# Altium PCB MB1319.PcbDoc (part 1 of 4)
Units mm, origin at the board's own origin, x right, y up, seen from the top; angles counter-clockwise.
Board outline 70 x 82.5 mm, 2 copper layers (Top Layer, Bottom Layer), stack 1.571 mm thick; 252 components, 179 nets, 814 pads, 1000 vias.
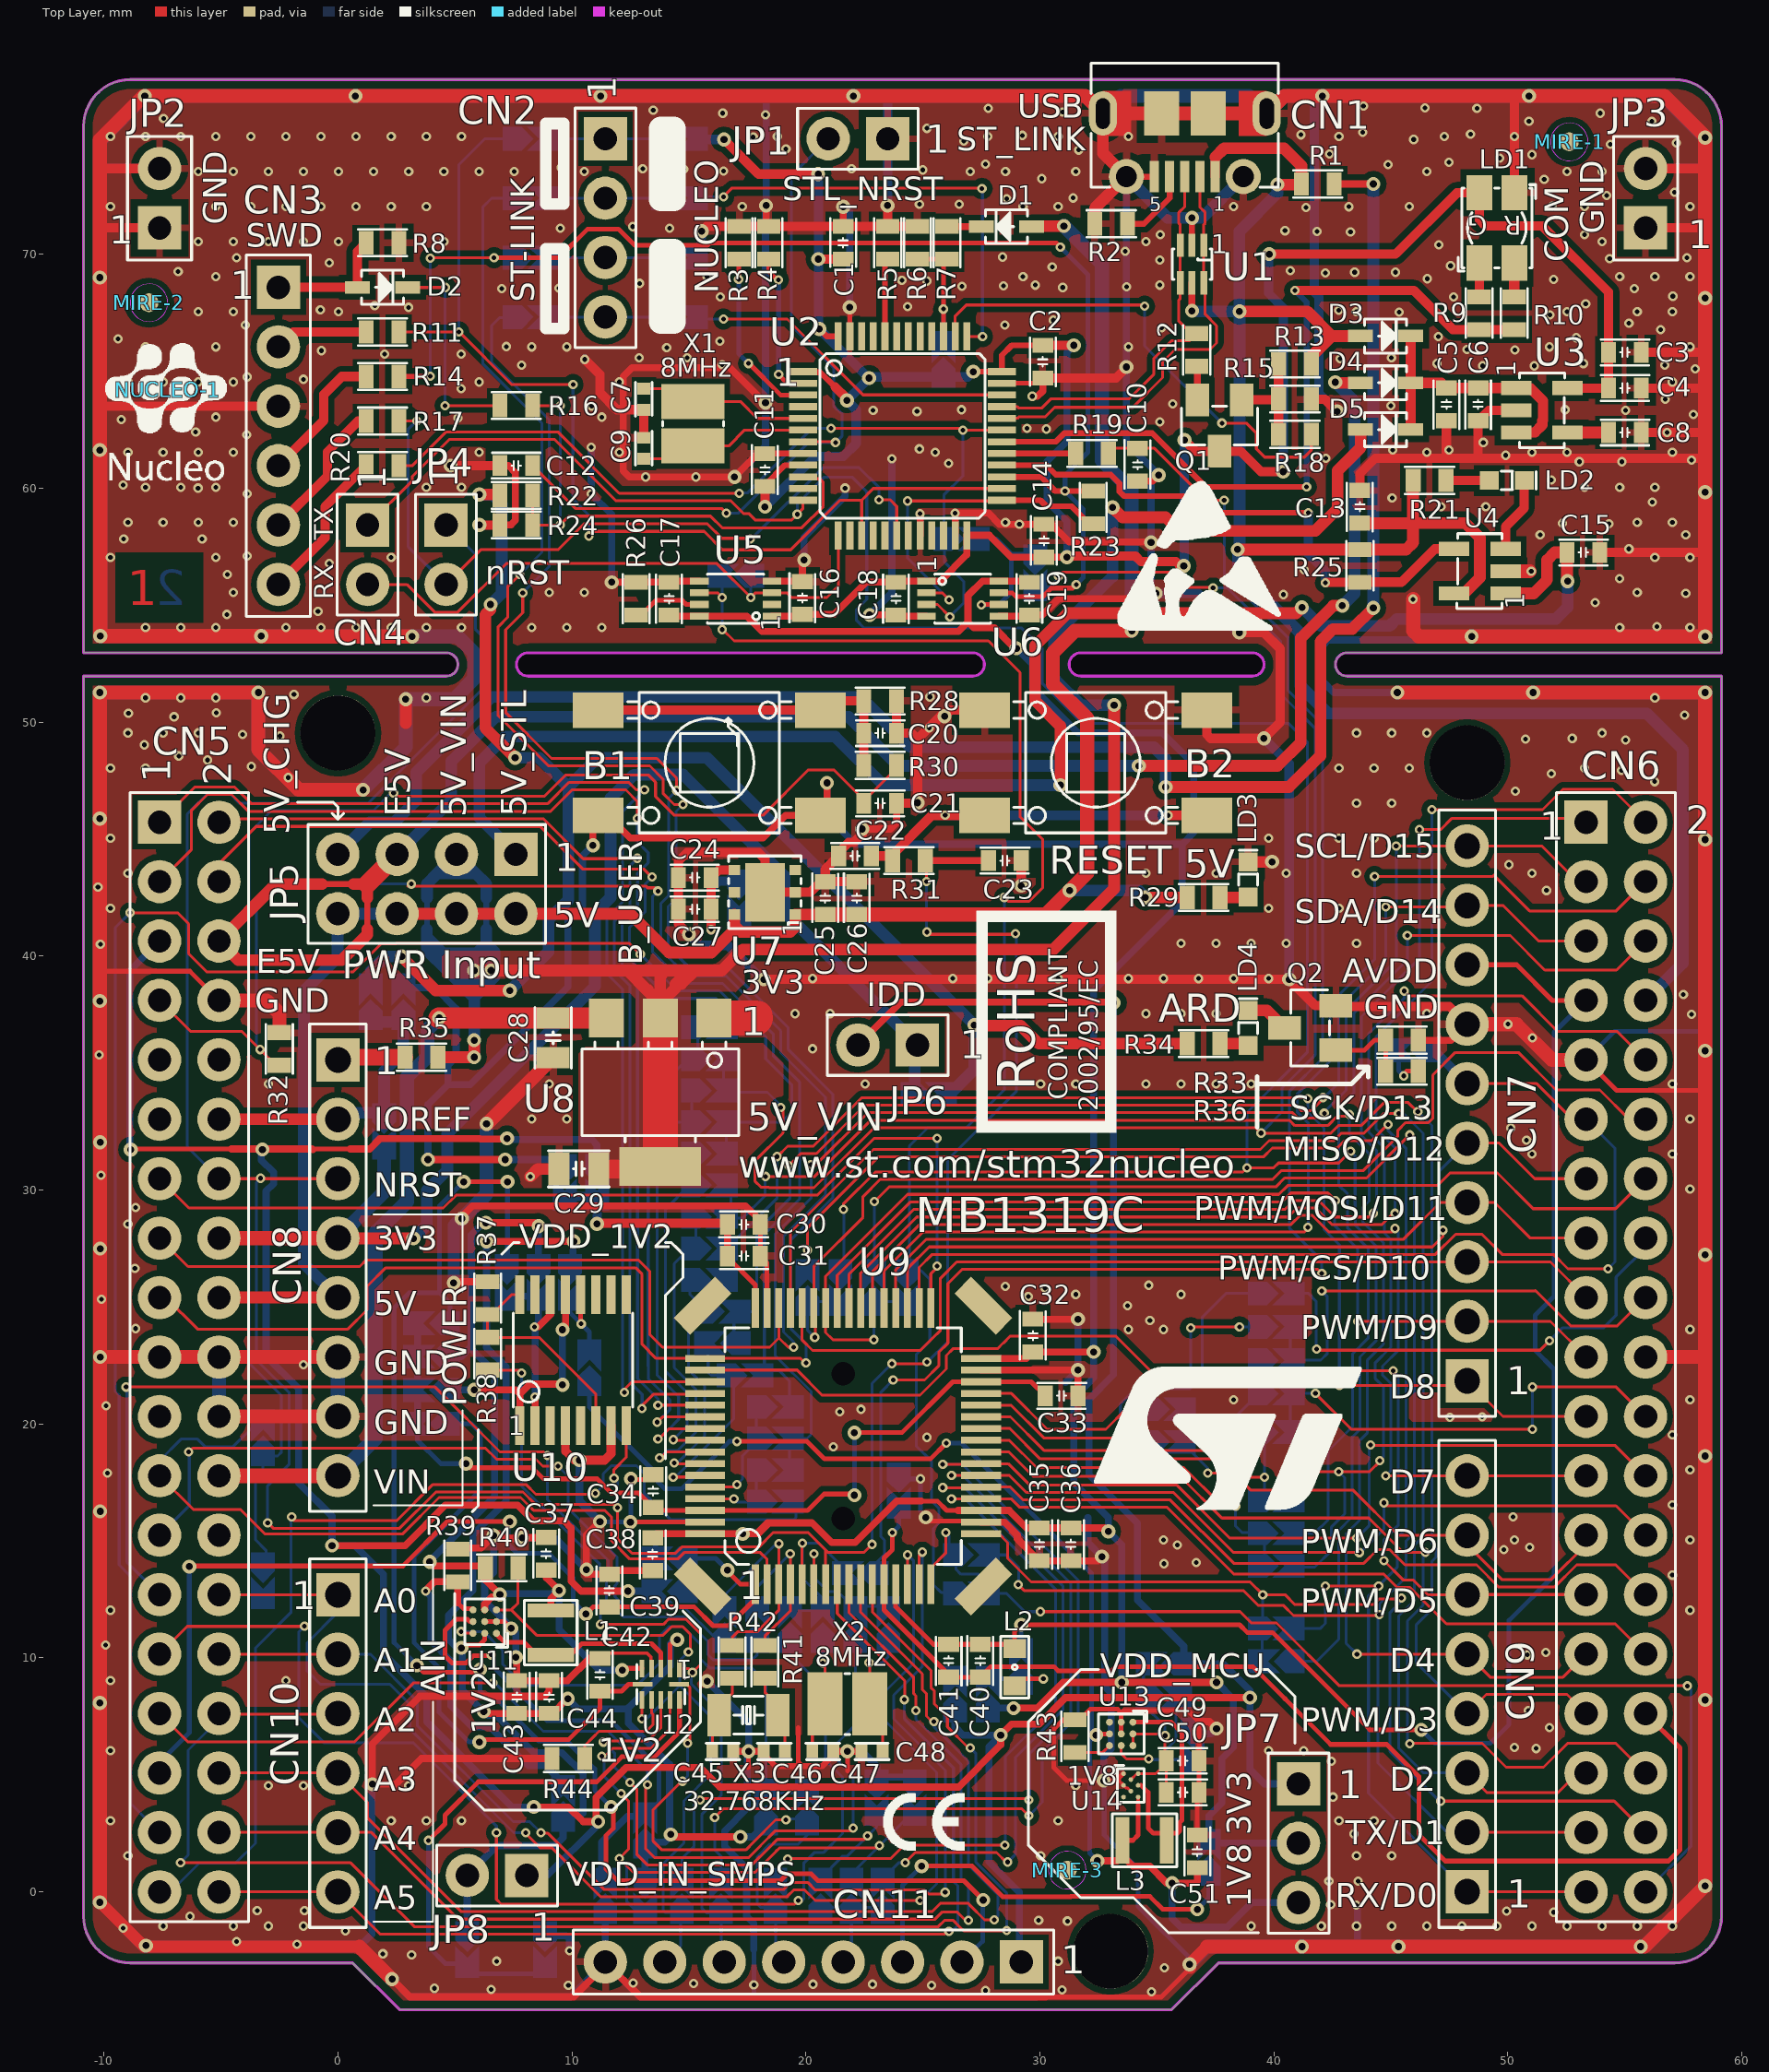
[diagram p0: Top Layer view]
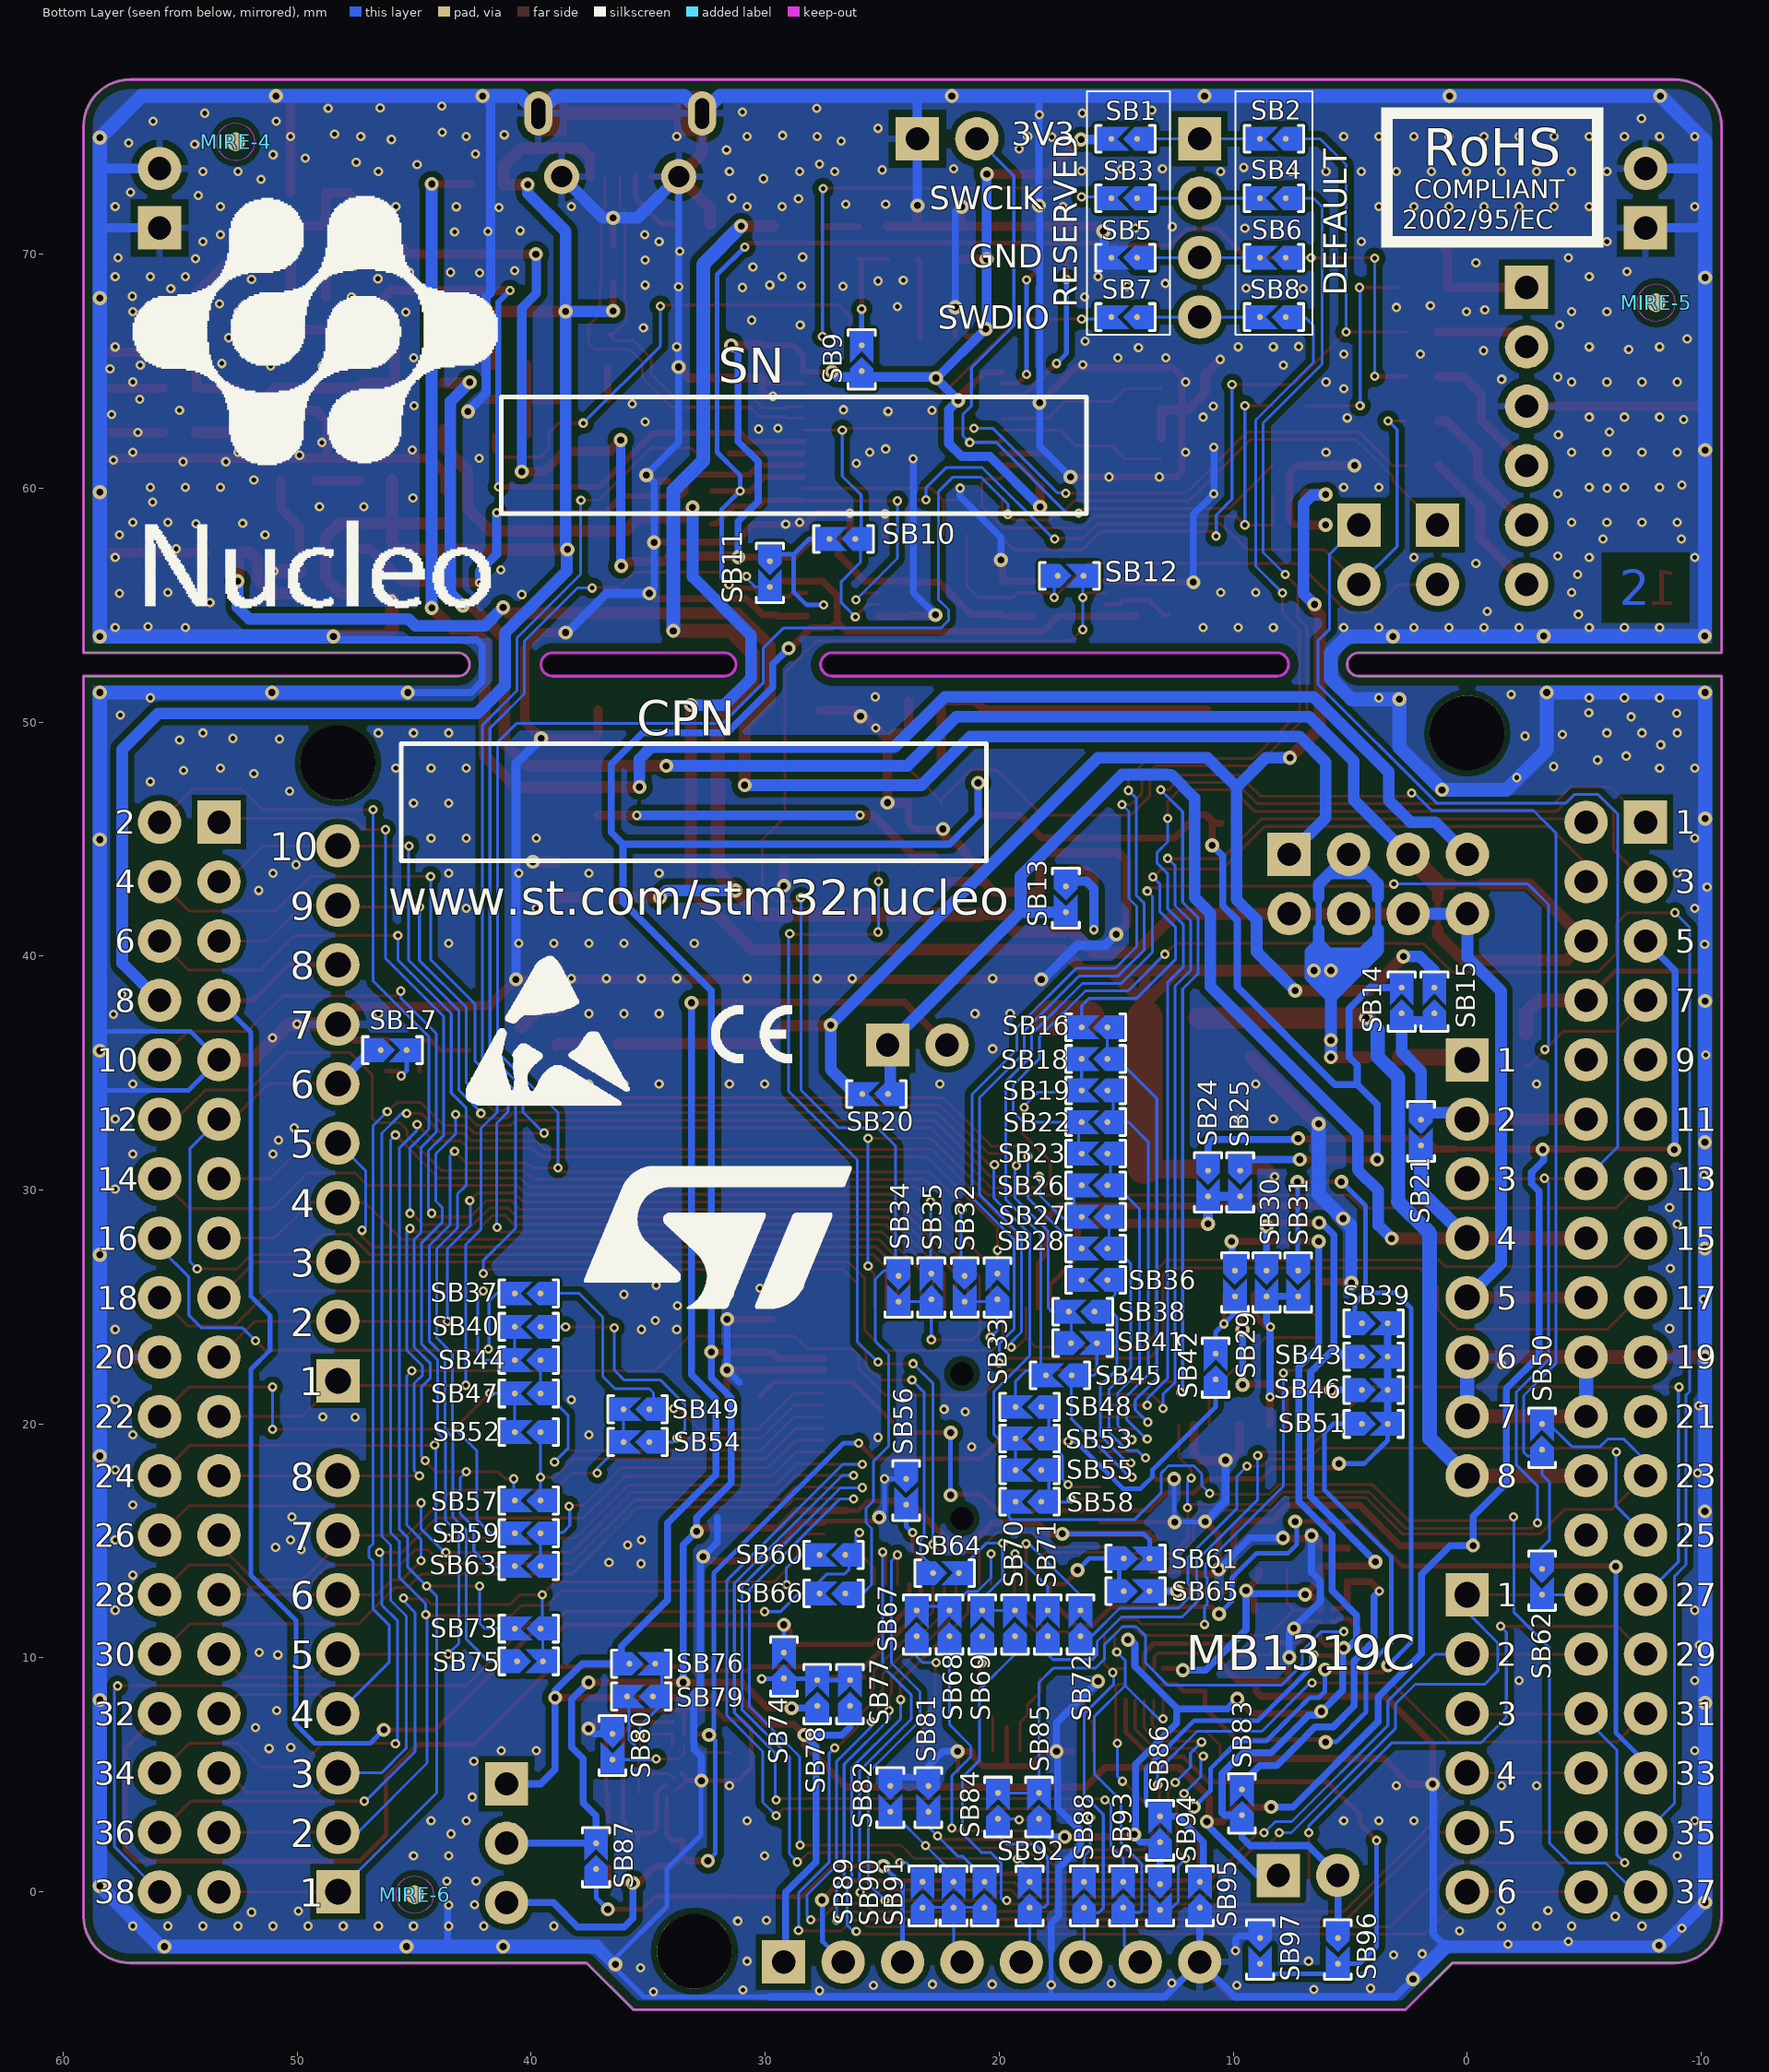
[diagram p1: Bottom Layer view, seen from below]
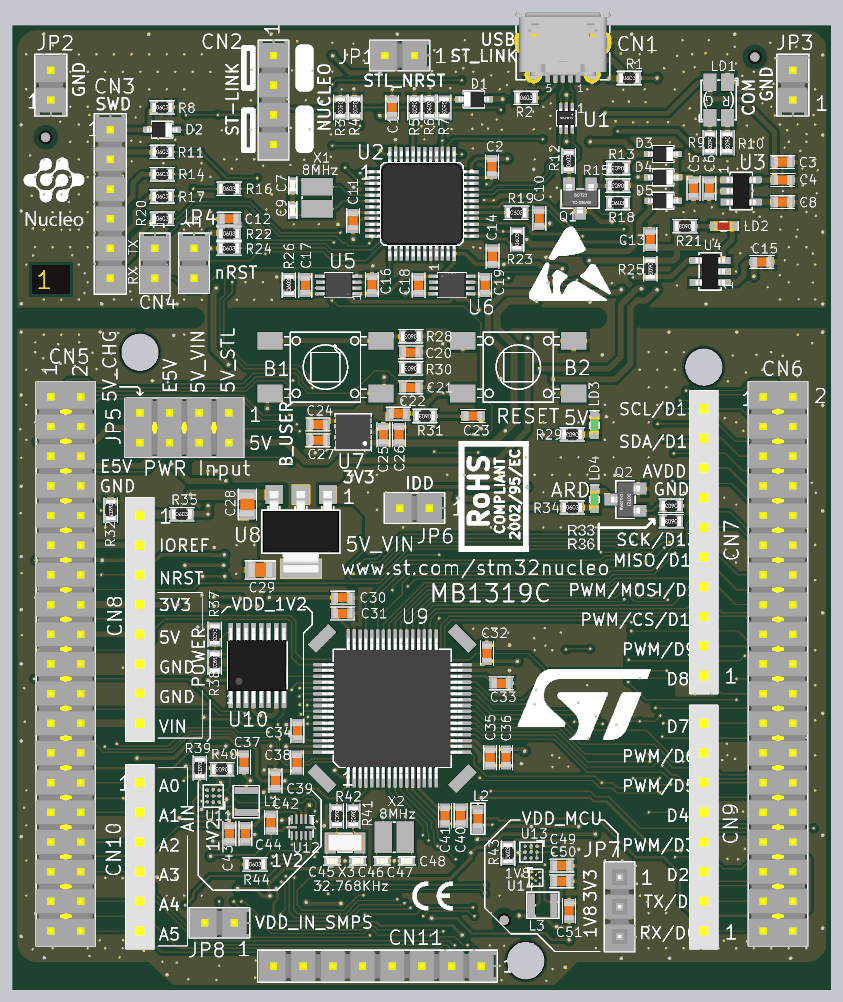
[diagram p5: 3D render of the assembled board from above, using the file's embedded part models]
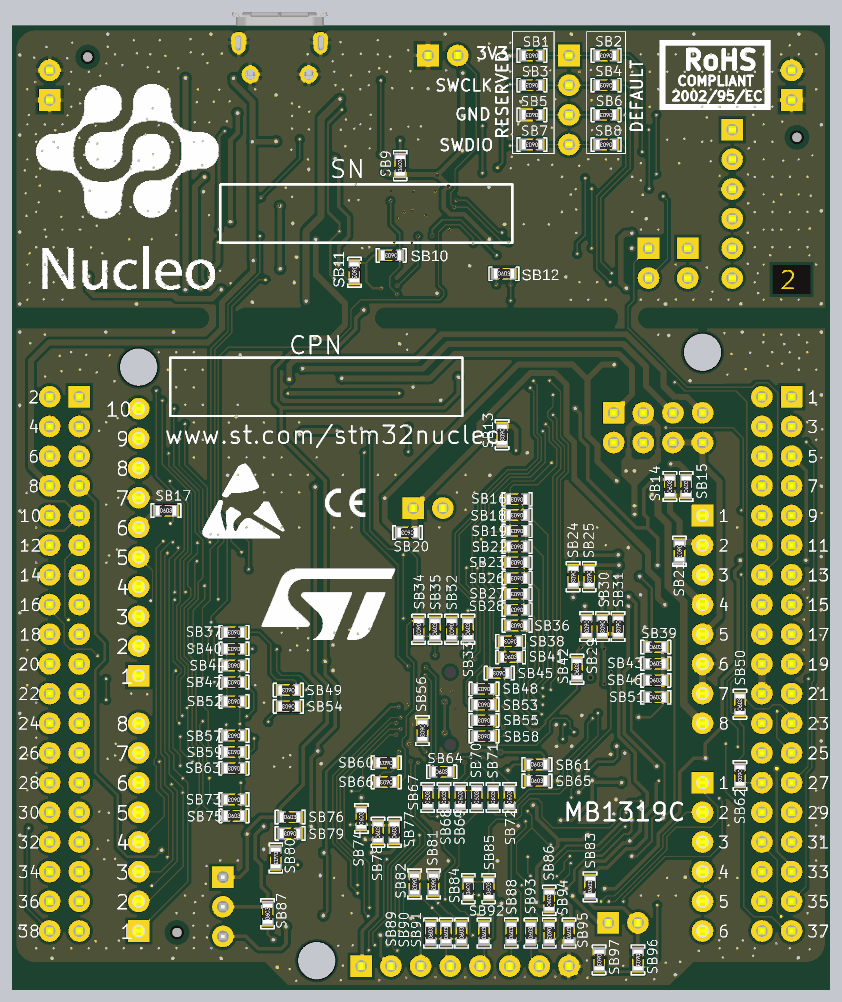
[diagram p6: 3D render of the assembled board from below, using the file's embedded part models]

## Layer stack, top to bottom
Top Solder: solder mask 0.0102, Solder Resist, Dk 3.5
Top Layer: signal copper 0.0356
Dielectric1: core 1.5, FR-4, Dk 4.8
Bottom Layer: signal copper 0.0356
Bottom Solder: solder mask 0.0102, Solder Resist, Dk 3.5

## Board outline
-8.87,-3.04 0.63,-3.04 2.63,-5.04 35.63,-5.04 37.63,-3.04 57.13,-3.04 ccw(c57.13,-1.04) 59.13,-1.04 59.13,51.96 43.13,51.96 cw(c43.13,52.46) 43.13,52.96 59.13,52.96 59.13,75.46 ccw(c57.13,75.46) 57.13,77.46 -8.87,77.46 ccw(c-8.87,75.46) -10.87,75.46 -10.87,52.96 4.63,52.96 cw(c4.63,52.46) 4.63,51.96 -10.87,51.96 -10.87,-1.04 ccw(c-8.87,-1.04)
cut-out: 31.75,52.96 ccw(c31.75,52.46) 31.25,52.46 ccw(c31.75,52.46) 31.75,51.96 39.08,51.96 ccw(c39.08,52.46) 39.58,52.46 ccw(c39.08,52.46) 39.08,52.96
cut-out: 8.13,52.96 ccw(c8.13,52.46) 7.63,52.46 ccw(c8.13,52.46) 8.13,51.96 27.13,51.96 ccw(c27.13,52.46) 27.63,52.46 ccw(c27.13,52.46) 27.13,52.96
cut-out: 8.13,52.96 27.13,52.96

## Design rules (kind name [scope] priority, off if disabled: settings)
BoardOutlineClearance [All] p1: gap=0.4 ignorepadtopadclearanceinfootprint=FALSE except(0.25: Text-OutlineEdge Text-CavityEdge Text-CutoutEdge Text-SplitBarrior Text-SplitContinuation)
Clearance Clearance_Poly [(InPoly)] p1: gap=0.25 ignorepadtopadclearanceinfootprint=FALSE except(0: Arc-Hole Track-Hole SMDPad-Hole THPad-Hole Via-Hole Fill-Hole Poly-Hole Region-Hole Text-Hole)
Clearance Clearance_SB [(HasFootprint('SB_DIP')) or (HasFootprint('JP2_SMD')) or InNet('PC13')] p2: gap=0.12 ignorepadtopadclearanceinfootprint=FALSE except(0: Arc-Hole Track-Hole SMDPad-Hole THPad-Hole Via-Hole Fill-Hole Poly-Hole Region-Hole Text-Hole)
Clearance [All] p3: gap=0.2 ignorepadtopadclearanceinfootprint=FALSE except(0: Arc-Hole Track-Hole SMDPad-Hole THPad-Hole Via-Hole Fill-Hole Poly-Hole Region-Hole Text-Hole; 0.15: Arc-Fill Arc-Poly Arc-Region Track-Fill Track-Poly Track-Region SMDPad-SMDPad SMDPad-Fill SMDPad-Poly SMDPad-Region THPad-Fill THPad-Poly THPad-Region Via-Fill Via-Poly Via-Region Fill-Fill Fill-Poly Fill-Region Poly-Poly Poly-Region Region-Region)
ComponentClearance [All] p1: gap=0.254 collisioncheckmode=3 verticalgap=0.254 showdistances=TRUE
DiffPairsRouting [All] p1: maxlimit=0.25 minlimit=0.25 mostfreqgap=0.25 substack1={6D7DF998-63A1-48DE-B83D-04AF5656AB54} toplayer_{6d7df998-63a1-48de-b83d-04af5656ab54}_minwidth=0.381 toplayer_{6d7df998-63a1-48de-b83d-04af5656ab54}_maxwidth=0.381 toplayer_{6d7df998-63a1-48de-b83d-04af5656ab54}_prefwidth=0.381 bottomlayer_{6d7df998-63a1-48de-b83d-04af5656ab54}_minwidth=0.381 bottomlayer_{6d7df998-63a1-48de-b83d-04af5656ab54}_maxwidth=0.381 bottomlayer_{6d7df998-63a1-48de-b83d-04af5656ab54}_prefwidth=0.381 toplayer_minwidth=0.12 toplayer_maxwidth=0.12 toplayer_prefwidth=0.12 bottomlayer_minwidth=0.12 bottomlayer_maxwidth=0.12 bottomlayer_prefwidth=0.12 substack2={5F282221-89D6-4411-BDE5-3C2755F118A8} toplayer_{5f282221-89d6-4411-bde5-3c2755f118a8}_minwidth=0.381 toplayer_{5f282221-89d6-4411-bde5-3c2755f118a8}_maxwidth=0.381 toplayer_{5f282221-89d6-4411-bde5-3c2755f118a8}_prefwidth=0.381 bottomlayer_{5f282221-89d6-4411-bde5-3c2755f118a8}_minwidth=0.381 bottomlayer_{5f282221-89d6-4411-bde5-3c2755f118a8}_maxwidth=0.381 bottomlayer_{5f282221-89d6-4411-bde5-3c2755f118a8}_prefwidth=0.381 maxuncoupledlength=12.7
FabricationTestPointUsage TestPointUsage [All] p1: valid=0 allowmultiple=FALSE
FabricationTestpoint Testpoint [(IsPad And (OnTopLayer Or OnBottomLayer))] p1: side=3 testpointundercomponent=TRUE minsize=1.016 maxsize=2.54 preferedsize=1.524 minholesize=0 maxholesize=1.016 preferedholesize=0.813 testpointgrid=0.025 allowsidetop=TRUE allowsidebottom=TRUE usegrid=TRUE gridtolerance=0
HoleSize [All] p1: absolutevalues=TRUE maxlimit=3.81 minlimit=0.025 maxpercent=80.000 minpercent=20.000
MinimumSolderMaskSliver [All] p1: minsoldermaskwidth=0.2
PolygonConnect 5V_VIN_L01_P000 [All vs IsNamedPolygon('5V_VIN_L01_P000')] p1: connectstyle=Direct reliefconductorwidth=0.254 reliefentries=4 polygonreliefangle="90 Angle" airgapwidth=0.254
PolygonConnect PolygonConnect_VIAS [IsVia] p2: connectstyle=Direct reliefconductorwidth=0.508 reliefentries=4 polygonreliefangle="90 Angle" airgapwidth=0.254
PolygonConnect [All] p3: connectstyle=Relief reliefconductorwidth=0.3 reliefentries=4 polygonreliefangle="90 Angle" airgapwidth=0.3
RoutingVias RoutingVias_VDD_MCU [InNet('VDD_MCU')] p1: holewidth=0.3 width=0.6 viastyle="Through Hole" minholewidth=0.3 minwidth=0.6 maxholewidth=0.3 maxwidth=0.6
RoutingVias RoutingVias_ALIMS [InNetClass('ALIMS')] p2: holewidth=0.3 width=0.6 viastyle="Through Hole" minholewidth=0.2 minwidth=0.4 maxholewidth=0.3 maxwidth=0.6
RoutingVias [All] p3: holewidth=0.2 width=0.4 viastyle="Through Hole" minholewidth=0.2 minwidth=0.4 maxholewidth=0.2 maxwidth=0.4
SilkToSolderMaskClearance SilkscreenOverComponentPads [IsPad] p1: minsilkscreentomaskgap=0.254 clearancetoexposedcopper=TRUE
SolderMaskExpansion [All] p1: expansion=0.102 istentingtop=FALSE
Width Width_ALIMS [InNetClass('ALIMS')] p1: maxlimit=5 minlimit=0.12 preferedwidth=0.2 substack1={6D7DF998-63A1-48DE-B83D-04AF5656AB54} substack2={5F282221-89D6-4411-BDE5-3C2755F118A8}
Width Width_VDD_MCU [InNet('VDD_MCU')] p2: maxlimit=5 minlimit=0.15 preferedwidth=0.3 substack1={6D7DF998-63A1-48DE-B83D-04AF5656AB54} substack2={5F282221-89D6-4411-BDE5-3C2755F118A8}
Width [All] p3: maxlimit=5 minlimit=0.12 preferedwidth=0.12 substack1={6D7DF998-63A1-48DE-B83D-04AF5656AB54} substack2={5F282221-89D6-4411-BDE5-3C2755F118A8} minimp=50.000000 maximp=50.000000 favimp=50.000000
23 further rules are at their usual default settings.

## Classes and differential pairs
net class PH[0..1]: PH0 PH1
component class U_STM32_microcontroller_power: C13 C17 C26 C30 C31 C32 C33 C36 C38 C39 C45 L2 SB16 SB18 SB34 SB56 SB65 SB68 SB77 SB82
component class "U_Power SMPS": C17 C18 C20 C28 C38 C42 C47 CN2 CN300 HW4 JP4 JP7 L2 L3 L300 L301 Q2 R36 R37 R39 R41 R43 SB23 SB27 SB29 SB39 SB40 SB43 SB46 SB51 SB56 SB64 SB76 SB79 SB80 SB81 SB82 SB83 SB84 SB85 SB86 SB87 SB88 SB89 SB90 SB92 SB93 SB94 U5 U8 U12 U13 U14 U301 U302 U303 U305
component class U_Power: C22 C24 C26 C31 C33 C39 JP5 JP6 LD3 SB48 SB69 U4 U9
component class U_ST_LINK_V2-1: C1 C2 C3 C4 C5 C6 C7 C8 C9 C10 C11 C12 C13 C14 C26 CN3 CN6 D1 D2 D3 D4 D5 JP1 JP2 JP3 JP5 LD1 LD2 Q2 R2 R3 R4 R5 R6 R7 R8 R9 R10 R11 R12 R13 R14 R15 R16 R17 R18 R19 R20 R21 R22 R23 R24 R25 SB1 SB3 SB4 SB5 SB6 SB7 SB8 SB9 SB69 U1 U2 U4 U8 X1
net class PA[0..15]: PA0 PA1 PA2 PA3 PA4 PA6 PA7 PA8 PA9 PA10 PA11 PA12 PA13 PA14 PA15
net class PB[0..15]: PB0 PB1 PB2 PB3 PB4 PB5 PB6 PB7 PB8 PB9 PB10 PB11 PB12 PB14 PB15
net class PC[0..15]: PC0 PC1 PC2 PC3 PC4 PC5 PC6 PC7 PC8 PC9 PC10 PC11 PC12 PC13 PC14 PC15
component class U_STM32_microcontroller_IOs: B1 B2 C14 C15 C17 C20 C22 C25 C26 C30 C31 C33 C38 C39 C41 C42 C45 C47 C48 JP7 R28 R29 R30 R31 R33 R42 SB7 SB14 SB16 SB17 SB18 SB19 SB20 SB22 SB23 SB25 SB26 SB27 SB30 SB32 SB33 SB34 SB35 SB36 SB37 SB38 SB40 SB41 SB42 SB44 SB45 SB47 SB48 SB50 SB52 SB53 SB54 SB55 SB57 SB58 SB60 SB61 SB66 SB67 SB68 SB69 SB72 SB77 SB80 SB82 U5 U8 X2 X3
component class U_Arduino_extension_connectors: CN2 CN5 CN6 CN7 CN8 CN9 LD2 Q2 R35 R42 SB14 SB17 SB22 SB67
net class ALIMS: 3V3 3V3_PER 3V3_ST_LINK 5V 5V_STLINK 5V_STLINK_SW 5V_USB_CHG 5V_VIN AGND AVDD E5V GND VBAT VDD VDD_1V2 VDD_1V2_SW VDD_IN_SMPS VDD_SMPS_1V2 VDD_SMPS_1V8 VDDUSB VIN VOUT2 VOUTCORE VOUTVDD
differential pair STLINK_USB_D: +STLINK_USB_D_P -STLINK_USB_D_N

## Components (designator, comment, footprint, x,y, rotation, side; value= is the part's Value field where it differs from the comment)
B1 ".designator" SWI_WEALTHMETAL_TD-0341_4P_BLUE 15.875,48.26 r90 top locked
B2 ".designator" SWI_WEALTHMETAL_TD-0341_4P_BLACK 32.385,48.26 r90 top locked
C1 ".designator" C0603 21.59,70.485 r270 top
C2 ".designator" C0603 30.125,65.4 r90 top
C3 ".designator" C0603 55,65.8 r180 top
C4 ".designator" C0603 55,64.275 r180 top
C5 ".designator" C0603 47.375,63.575 r90 top
C6 ".designator" C0603 48.725,63.575 r90 top
C7 ".designator" C0402 13.075,63.8 r270 top
C8 ".designator" C0603 55,62.375 r180 top
C9 ".designator" C0402 13.075,61.7 r90 top
C10 ".designator" C0603 34.175,61 r270 top
C11 ".designator" C0603 18.25,60.775 r270 top
C12 ".designator" C0603 7.62,60.96 r0 top
C13 ".designator" C0603 43.675,59.2 r90 top
C14 ".designator" C0603 30.175,57.75 r270 top
C15 ".designator" C0603 53.225,57.25 r180 top
C16 ".designator" C0603 19.85,55.3 r270 top
C17 ".designator" C0603 14.15,55.275 r90 top
C18 "C18" C0603 23.85,55.275 r90 top
C19 "C19" C0603 29.55,55.275 r270 top
C20 ".designator" C0603 23.175,49.525 r180 top
C21 ".designator" C0603 23.175,46.525 r180 top
C22 ".designator" C0603 22.1,44.275 r0 top
C23 ".designator" C0603 28.5,44.075 r180 top
C24 ".designator" C0603 15.25,43.35 r0 top
C25 ".designator" C0603 20.825,42.475 r270 top
C26 ".designator" C0603 22.175,42.475 r270 top
C27 ".designator" C0603 15.25,42 r0 top
C28 ".designator" C0805 9.2,36.5 r90 top
C29 ".designator" C0805 10.3,30.9 r0 top
C30 ".designator" C0603 17.35,28.525 r0 top
C31 ".designator" C0603 17.35,27.175 r180 top
C32 ".designator" C0603 29.7,23.775 r270 top
C33 ".designator" C0603 30.925,21.2 r180 top
C34 ".designator" C0603 13.475,17.125 r270 top
C35 ".designator" C0603 29.975,14.85 r90 top
C36 ".designator" C0603 31.325,14.85 r90 top
C37 ".designator" C0603 8.9,14.45 r270 top
C38 ".designator" C0603 13.45,14.425 r90 top
C39 ".designator" C0603 11.6,12.875 r90 top
C40 ".designator" C0603 27.45,9.875 r270 top
C41 ".designator" C0603 26.1,9.875 r90 top
C42 ".designator" C0603 11.2,9.275 r270 top
C43 ".designator" C0603 7.65,8.325 r270 top
C44 ".designator" C0603 9.025,8.325 r270 top
C45 ".designator" C0402 16.45,6 r0 top
C46 "C46" C0402 18.65,6 r180 top
C47 "C47" C0402 20.725,6 r180 top
C48 "C48" C0402 22.825,6 r0 top
C49 ".designator" C0603 36.1,5.6 r180 top
C50 ".designator" C0603 36.1,4.25 r180 top
C51 ".designator" C0603 36.725,1.725 r270 top
CARTOUCHE-BOT1 ".designator" CARTOUCHE_STM_BOTTOM -34.7,-40.775 r0 top
CARTOUCHE-TOP1 ".designator" CARTOUCHE_STM_TOP -34.775,-40.8 r0 top
CN1 ".designator" CON_USBMICROB_MOLEX_105017-0001_H2P90 36.195,77.46 r180 top locked
CN2 "CN2" CON_SAMTEC_TSW-104-07-G-S 11.43,71.12 r270 top locked
CN3 ".designator" CON_SAMTEC_TSW-106-07-X-S -2.54,62.23 r270 top locked
CN4 ".designator" CON_SAMTEC_TSW-102-07-G-S 1.27,57.15 r270 top locked
CN5 ".designator" CON_SAMTEC_TSW-119-09-X-D -6.35,22.86 r270 top locked
CN6 ".designator" CON_SAMTEC_TSW-119-09-X-D 54.61,22.86 r270 top locked
CN7 ".designator" CON_SAMTEC_SSW-110-03-X-S 48.26,33.274 r90 top locked
CN8 ".designator" CON_SAMTEC_SSW-108-03-X-S 0,26.67 r270 top locked
CN9 ".designator" CON_SAMTEC_SSW-108-03-X-S 48.26,8.89 r90 top locked
CN10 ".designator" CON_SAMTEC_SSW-106-03-X-S 0,6.35 r270 top locked
CN11 ".designator" CON_SAMTEC_TSW-108-07-X-S 20.32,-3 r180 top
D1 ".designator" DIO_SOD323 28.575,71.175 r180 top
D2 ".designator" DIO_SOD323 1.905,68.58 r0 top
D3 ".designator" DIO_SOD323 44.775,66.5 r0 top
D4 ".designator" DIO_SOD323 44.775,64.5 r0 top
D5 ".designator" DIO_SOD323 44.775,62.5 r0 top
JP1 ".designator" CON_SAMTEC_TSW-102-07-G-S 22.225,74.93 r180 top
JP2 ".designator" CON_SAMTEC_TSW-102-09-X-S -7.62,72.39 r90 top locked
JP3 ".designator" CON_SAMTEC_TSW-102-09-X-S 55.88,72.39 r90 top locked
JP4 ".designator" CON_SAMTEC_TSW-102-07-G-S 4.625,57.15 r270 top locked
JP5 ".designator" CON_SAMTEC_TSW-104-07-X-D 3.8,43.075 r180 top locked
JP6 ".designator" CON_SAMTEC_TSW-102-07-G-S 23.495,36.195 r180 top locked
JP7 ".designator" CON_SAMTEC_TSW-103-07-F-S 41.05,2.075 r270 top locked
JP8 ".designator" CON_SAMTEC_TSW-102-07-G-S 6.8,0.7 r180 top locked
L1 ".designator" IND_TDK_VLS252010HBX-1 9.1,11.075 r90 top
L2 ".designator" L0603 28.925,9.6 r90 top
L3 ".designator" IND_TDK_VLS252010HBX-1 34.475,2.2 r180 top
LD1 ".designator" LED_BI-GR_HSMF-A201-A00J1 49.53,71.12 r180 top locked
LD2 ".designator" LED_0603_RED 49.95,60.325 r0 top
LD3 ".designator" LED_0603_GREEN 38.9,43.275 r90 top
LD4 ".designator" LED_0603_GREEN 38.9,36.925 r90 top
MIRE-1 ".designator" MIRE_PLACE_SMD_0P8MM 52.625,74.8 r90 top
MIRE-2 ".designator" MIRE_PLACE_SMD_0P8MM -8.075,67.925 r90 top
MIRE-3 ".designator" MIRE_PLACE_SMD_0P8MM 31.175,0.925 r90 top
MIRE-4 ".designator" MIRE_PLACE_SMD_0P8MM 52.625,74.8 r90 bottom
MIRE-5 ".designator" MIRE_PLACE_SMD_0P8MM -8.075,67.925 r90 bottom
MIRE-6 ".designator" MIRE_PLACE_SMD_0P8MM 44.975,-0.125 r90 bottom
NUCLEO-1 ".designator" "NUCLEO_black 0.5cm" -7.275,64.2 r0 top
Q1 ".designator" NPN_SOT23 37.675,62.675 r180 top
Q2 ".designator" NPN_SOT23 41.55,36.925 r90 top
R1 ".designator" R0603 41.875,73 r0 top
R2 ".designator" R0603 33.05,71.3 r0 top
R3 ".designator" R0603 17.145,70.485 r270 top
R4 ".designator" R0603 18.415,70.485 r270 top
R5 ".designator" R0603 23.495,70.485 r270 top
R6 ".designator" R0603 24.765,70.485 r90 top
R7 ".designator" R0603 26.035,70.485 r270 top
R8 ".designator" R0603 1.905,70.485 r0 top
R9 "R9" R0603 48.775,67.475 r270 top
R10 "R10" R0603 50.275,67.475 r270 top
R11 ".designator" R0603 1.905,66.675 r0 top
R12 ".designator" R0603 36.7,65.9 r90 top
R13 "R13" R0603 40.9,65.3 r180 top
R14 ".designator" R0603 1.905,64.77 r0 top
R15 "R15" R0603 40.9,63.8 r180 top
R16 ".designator" R0603 7.625,63.525 r0 top
R17 ".designator" R0603 1.905,62.865 r0 top
R18 "R18" R0603 40.9,62.3 r0 top
R19 "R19" R0603 32.225,61.475 r0 top
R20 ".designator" R0603 1.905,60.96 r0 top
R21 ".designator" R0603 46.65,60.325 r180 top
R22 ".designator" R0603 7.62,59.69 r0 top
R23 ".designator" R0603 32.275,59.175 r90 top
R24 ".designator" R0603 7.62,58.42 r0 top
R25 ".designator" R0603 43.675,56.675 r270 top
R26 ".designator" R0603 12.75,55.275 r90 top
R28 ".designator" R0603 23.175,50.9 r180 top
R29 ".designator" R0603 37,42.5 r180 top
R30 ".designator" R0603 23.175,48.15 r180 top
R31 ".designator" R0603 24.4,44.075 r180 top
R32 ".designator" R0603 -2.5,36.025 r270 top
R33 "R33" R0603 45.475,36.4 r180 top
R34 "R34" R0603 37,36.25 r0 top
R35 ".designator" R0603 3.575,35.675 r0 top
R36 "R36" R0603 45.475,35.075 r180 top
R37 ".designator" R0603 6.4,25.375 r270 top
R38 ".designator" R0603 6.4,23 r270 top
R39 ".designator" R0603 5.125,13.95 r270 top
R40 ".designator" R0603 7,13.85 r180 top
R41 ".designator" R0603 18.25,9.825 r270 top
R42 ".designator" R0603 16.85,9.825 r270 top
R43 ".designator" R0603 31.5,6.65 r90 top
R44 ".designator" R0603 9.85,5.7 r0 top
SB1 ".designator" SOLDER-BRIDGE_R0603-0R 14.605,74.93 r0 bottom
SB2 ".designator" SOLDER-BRIDGE_R0603-0R 8.255,74.93 r0 bottom
SB3 ".designator" SOLDER-BRIDGE_R0603-0R 14.605,72.39 r0 bottom
SB4 ".designator" SOLDER-BRIDGE_R0603-0R 8.255,72.39 r0 bottom
SB5 ".designator" SOLDER-BRIDGE_R0603-0R 14.605,69.85 r0 bottom
SB6 ".designator" SOLDER-BRIDGE_R0603-0R 8.255,69.85 r0 bottom
SB7 ".designator" SOLDER-BRIDGE_R0603-0R 14.605,67.31 r0 bottom
SB8 ".designator" SOLDER-BRIDGE_R0603-0R 8.255,67.31 r0 bottom
SB9 "SB9" SOLDER-BRIDGE_R0603-0R 25.875,65.5 r90 bottom
SB10 "SB10" SOLDER-BRIDGE_R0603-0R 26.65,57.825 r0 bottom
SB11 "SB11" SOLDER-BRIDGE_R0603-0R 29.8,56.375 r270 bottom
SB12 "SB12" SOLDER-BRIDGE_R0603-0R 17,56.25 r180 bottom
SB13 ".designator" SOLDER-BRIDGE_R0603-0R 17.15,42.475 r270 bottom
SB14 ".designator" SOLDER-BRIDGE_R0603-0R 2.8,38.05 r90 bottom
SB15 ".designator" SOLDER-BRIDGE_R0603-0R 1.4,38.05 r90 bottom
SB16 ".designator" SOLDER-BRIDGE_R0603-0R 15.875,36.95 r0 bottom
SB17 ".designator" SOLDER-BRIDGE_R0603-0R 45.925,35.975 r180 bottom
SB18 ".designator" SOLDER-BRIDGE_R0603-0R 15.875,35.6 r0 bottom
SB19 ".designator" SOLDER-BRIDGE_R0603-0R 15.875,34.25 r0 bottom
SB20 ".designator" SOLDER-BRIDGE_R0603-0R 25.25,34.1 r0 bottom
SB21 ".designator" SOLDER-BRIDGE_R0603-0R 1.975,32.5 r270 bottom
SB22 ".designator" SOLDER-BRIDGE_R0603-0R 15.875,32.9 r0 bottom
SB23 ".designator" SOLDER-BRIDGE_R0603-0R 15.875,31.55 r0 bottom
SB24 ".designator" SOLDER-BRIDGE_R0603-0R 11.075,30.325 r270 bottom
SB25 ".designator" SOLDER-BRIDGE_R0603-0R 9.7,30.325 r270 bottom
SB26 ".designator" SOLDER-BRIDGE_R0603-0R 15.875,30.2 r0 bottom
SB27 ".designator" SOLDER-BRIDGE_R0603-0R 15.875,28.85 r0 bottom
SB28 ".designator" SOLDER-BRIDGE_R0603-0R 15.875,27.5 r0 bottom
SB29 ".designator" SOLDER-BRIDGE_R0603-0R 9.925,26.05 r270 bottom
SB30 ".designator" SOLDER-BRIDGE_R0603-0R 8.575,26.05 r270 bottom
SB31 ".designator" SOLDER-BRIDGE_R0603-0R 7.225,26.05 r270 bottom
SB32 ".designator" SOLDER-BRIDGE_R0603-0R 21.475,25.825 r270 bottom
SB33 ".designator" SOLDER-BRIDGE_R0603-0R 20.075,25.825 r90 bottom
SB34 ".designator" SOLDER-BRIDGE_R0603-0R 24.3,25.825 r270 bottom
SB35 ".designator" SOLDER-BRIDGE_R0603-0R 22.9,25.825 r90 bottom
SB36 ".designator" SOLDER-BRIDGE_R0603-0R 15.875,26.15 r0 bottom
SB37 ".designator" SOLDER-BRIDGE_R0603-0R 40.1,25.575 r0 bottom
SB38 ".designator" SOLDER-BRIDGE_R0603-0R 16.425,24.8 r0 bottom
SB39 "SB39" SOLDER-BRIDGE_R0603-0R 4,24.3 r180 bottom
SB40 ".designator" SOLDER-BRIDGE_R0603-0R 40.1,24.15 r0 bottom
SB41 ".designator" SOLDER-BRIDGE_R0603-0R 16.425,23.45 r180 bottom
SB42 ".designator" SOLDER-BRIDGE_R0603-0R 10.75,22.4 r90 bottom
SB43 "SB43" SOLDER-BRIDGE_R0603-0R 4,22.875 r180 bottom
SB44 ".designator" SOLDER-BRIDGE_R0603-0R 40.1,22.725 r0 bottom
SB45 ".designator" SOLDER-BRIDGE_R0603-0R 17.4,22.075 r0 bottom
SB46 "SB46" SOLDER-BRIDGE_R0603-0R 4,21.45 r180 bottom
SB47 ".designator" SOLDER-BRIDGE_R0603-0R 40.1,21.3 r0 bottom
SB48 ".designator" SOLDER-BRIDGE_R0603-0R 18.7,20.725 r0 bottom
SB49 ".designator" SOLDER-BRIDGE_R0603-0R 35.45,20.625 r0 bottom
SB50 "SB50" SOLDER-BRIDGE_R0603-0R -3.2,19.4 r90 bottom
SB51 "SB51" SOLDER-BRIDGE_R0603-0R 4,20 r180 bottom
SB52 ".designator" SOLDER-BRIDGE_R0603-0R 40.1,19.65 r0 bottom
SB53 ".designator" SOLDER-BRIDGE_R0603-0R 18.7,19.375 r0 bottom
SB54 ".designator" SOLDER-BRIDGE_R0603-0R 35.45,19.225 r0 bottom
SB55 ".designator" SOLDER-BRIDGE_R0603-0R 18.7,18.025 r0 bottom
SB56 ".designator" SOLDER-BRIDGE_R0603-0R 23.975,17.15 r270 bottom
SB57 ".designator" SOLDER-BRIDGE_R0603-0R 40.1,16.725 r0 bottom
SB58 ".designator" SOLDER-BRIDGE_R0603-0R 18.7,16.675 r0 bottom
SB59 ".designator" SOLDER-BRIDGE_R0603-0R 40.1,15.325 r0 bottom
SB60 ".designator" SOLDER-BRIDGE_R0603-0R 27.075,14.4 r0 bottom
SB61 ".designator" SOLDER-BRIDGE_R0603-0R 14.175,14.25 r180 bottom
SB62 "SB62" SOLDER-BRIDGE_R0603-0R -3.2,13.3 r270 bottom
SB63 ".designator" SOLDER-BRIDGE_R0603-0R 40.1,13.925 r0 bottom
SB64 "SB64" SOLDER-BRIDGE_R0603-0R 22.325,13.625 r180 bottom
SB65 ".designator" SOLDER-BRIDGE_R0603-0R 14.175,12.85 r180 bottom
SB66 ".designator" SOLDER-BRIDGE_R0603-0R 27.075,12.75 r0 bottom
SB67 ".designator" SOLDER-BRIDGE_R0603-0R 23.525,11.425 r90 bottom
SB68 ".designator" SOLDER-BRIDGE_R0603-0R 22.125,11.425 r90 bottom
SB69 ".designator" SOLDER-BRIDGE_R0603-0R 20.725,11.425 r90 bottom
SB70 ".designator" SOLDER-BRIDGE_R0603-0R 19.325,11.425 r90 bottom
SB71 ".designator" SOLDER-BRIDGE_R0603-0R 17.925,11.425 r90 bottom
SB72 ".designator" SOLDER-BRIDGE_R0603-0R 16.525,11.425 r90 bottom
SB73 ".designator" SOLDER-BRIDGE_R0603-0R 40.1,11.25 r0 bottom
SB74 "SB74" SOLDER-BRIDGE_R0603-0R 29.2,9.625 r90 bottom
SB75 ".designator" SOLDER-BRIDGE_R0603-0R 40.1,9.85 r180 bottom
SB76 ".designator" SOLDER-BRIDGE_R0603-0R 35.3,9.75 r180 bottom
SB77 ".designator" SOLDER-BRIDGE_R0603-0R 26.375,8.45 r90 bottom
SB78 ".designator" SOLDER-BRIDGE_R0603-0R 27.775,8.45 r90 bottom
SB79 ".designator" SOLDER-BRIDGE_R0603-0R 35.3,8.35 r0 bottom
SB80 ".designator" SOLDER-BRIDGE_R0603-0R 36.525,6.25 r270 bottom
SB81 ".designator" SOLDER-BRIDGE_R0603-0R 23.025,4.025 r270 bottom
SB82 ".designator" SOLDER-BRIDGE_R0603-0R 24.65,4.025 r270 bottom
SB83 ".designator" SOLDER-BRIDGE_R0603-0R 9.625,3.775 r90 bottom
SB84 ".designator" SOLDER-BRIDGE_R0603-0R 20.05,3.625 r90 bottom
SB85 ".designator" SOLDER-BRIDGE_R0603-0R 18.3,3.625 r90 bottom
SB86 ".designator" SOLDER-BRIDGE_R0603-0R 13.125,2.625 r90 bottom
SB87 ".designator" SOLDER-BRIDGE_R0603-0R 37.225,1.475 r90 bottom
SB88 ".designator" SOLDER-BRIDGE_R0603-0R 16.375,-0.175 r90 bottom locked
SB89 ".designator" SOLDER-BRIDGE_R0603-0R 23.275,-0.175 r90 bottom locked
SB90 ".designator" SOLDER-BRIDGE_R0603-0R 21.95,-0.175 r90 bottom
SB91 ".designator" SOLDER-BRIDGE_R0603-0R 20.625,-0.175 r90 bottom
SB92 ".designator" SOLDER-BRIDGE_R0603-0R 18.7,-0.175 r90 bottom locked
SB93 ".designator" SOLDER-BRIDGE_R0603-0R 14.7,-0.175 r90 bottom
SB94 ".designator" SOLDER-BRIDGE_R0603-0R 13.125,-0.175 r270 bottom
SB95 ".designator" SOLDER-BRIDGE_R0603-0R 11.425,-0.175 r90 bottom
SB96 "SB96" SOLDER-BRIDGE_R0603-0R 5.525,-2.475 r270 bottom
SB97 "SB97" SOLDER-BRIDGE_R0603-0R 8.85,-2.475 r270 bottom
U1 ".designator" ESD_SOT666 36.5,69.575 r180 top
U2 ".designator" ICC_LQFP48_7X7_P050 24.13,62.23 r270 top locked
U3 ".designator" REG_SOT23-5L 51.45,63.325 r270 top
U4 "U4" MOS_SOT23-5L 48.8,56.45 r90 top
U5 ".designator" ICC_VSSOP8_DCU_R-PDSO-G8_2X2P30_P050 17,55.275 r90 top
U6 ".designator" ICC_VSSOP8_DCU_R-PDSO-G8_2X2P30_P050 26.7,55.275 r270 top
U7 ".designator" ICC_DFN6-EPAD_3X3_P095 18.25,42.725 r90 top
U8 ".designator" REG_SOT223-TAB 13.775,34.175 r180 top locked
U9 ".designator" ICC_LQFP64_10X10_P050_SOCKET_YAMAICHI_IC149-064-069-B5_NM 21.59,19.05 r0 top locked
U10 ".designator" ICC_TSSOP16_5P1X4P5_P065 10.05,22.725 r90 top
U11 ".designator" ICC_WLCSP9_1P65X1P87_P050 6.275,11.55 r180 top
U12 ".designator" ICC_TQFN12_2X1P7_P040 13.8,8.875 r180 top
U13 ".designator" ICC_WLCSP9_1P65X1P87_P050 33.475,6.75 r270 top
U14 ".designator" ICC_FLIP-CHIP-BGA8_1P11X1P41_P040 33.888,4.55 r0 top
X1 ".designator" CRY_NX3225GD_2P 15.175,62.75 r90 top
X2 ".designator" CRY_NX3225GD_2P 21.775,8.025 r180 top
X3 ".designator" CRY_NX3215SA_2P 17.55,7.55 r0 top

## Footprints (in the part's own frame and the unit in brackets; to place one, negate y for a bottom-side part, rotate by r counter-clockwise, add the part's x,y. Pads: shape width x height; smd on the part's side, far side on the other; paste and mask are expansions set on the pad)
C0402 [mm]
  rect 0.51x0.56 smd mask+0.05: 1(-0.45,0) 2(0.45,0)
  silkscreen extent -0.72,-0.35 0.72,0.35, body extent -0.5,-0.3 0.5,0.3, height 0.4
C0603 [mm]
  rect 0.64x0.89 smd mask+0.05: 1(-0.7,0) 2(0.7,0)
  silkscreen extent -1.05,-0.55 1.02,0.55, body extent -0.9,-0.5 0.9,0.5, height 1.4
C0805 [mm]
  rect 0.9x1.4 smd mask+0.05: 1(-0.85,0) 2(0.85,0)
  silkscreen extent -1.3,-0.77 1.3,0.77, body extent -1.1,-0.7 1.1,0.7, height 1.35
CARTOUCHE_STM_BOTTOM [mm]
CARTOUCHE_STM_TOP [mm]
CON_SAMTEC_SSW-106-03-X-S [mm]
  rect 1.85x1.85 / inner round 1.85 / far side rect 1.85x1.85 hole 1.1 mask+0.05: 1(-6.35,0)
  round 1.85 hole 1.1 mask+0.05: 2(-3.81,0) 3(-1.27,0) 4(1.27,0) 5(3.81,0) 6(6.35,0)
  silkscreen extent -7.88,-1.2 7.88,1.2, body extent -7.88,-1.21 7.88,1.21, height 8.51
CON_SAMTEC_SSW-108-03-X-S [mm]
  rect 1.85x1.85 / inner round 1.85 / far side rect 1.85x1.85 hole 1.1 mask+0.05: 1(-8.89,0)
  round 1.85 hole 1.1 mask+0.05: 2(-6.35,0) 3(-3.81,0) 4(-1.27,0) 5(1.27,0) 6(3.81,0) 7(6.35,0) 8(8.89,0)
  silkscreen extent -10.42,-1.2 10.42,1.2, body extent -10.42,-1.21 10.42,1.21, height 8.51
CON_SAMTEC_SSW-110-03-X-S [mm]
  rect 1.85x1.85 / inner round 1.85 / far side rect 1.85x1.85 hole 1.1 mask+0.05: 1(-11.43,0)
  round 1.85 hole 1.1 mask+0.05: 2(-8.89,0) 3(-6.35,0) 4(-3.81,0) 5(-1.27,0) 6(1.27,0) 7(3.81,0) 8(6.35,0) 9(8.89,0) 10(11.43,0)
  silkscreen extent -12.96,-1.2 12.96,1.2, body extent -12.96,-1.21 12.96,1.21, height 8.51
CON_SAMTEC_TSW-102-07-G-S [mm]
  rect 1.85x1.85 / inner round 1.85 / far side rect 1.85x1.85 hole 1 mask+0.05: 1(-1.27,0)
  round 1.85 hole 1 mask+0.05: 2(1.27,0)
  silkscreen extent -2.58,-1.3 2.58,1.3, body extent -2.67,-1.3 2.58,1.3, height 8.38
CON_SAMTEC_TSW-102-09-X-S [mm]
  rect 1.85x1.85 / inner round 1.85 / far side rect 1.85x1.85 hole 1 mask+0.05: 1(-1.27,0)
  round 1.85 hole 1 mask+0.05: 2(1.27,0)
  silkscreen extent -2.64,-1.37 2.64,1.37, body extent -2.67,-1.3 2.58,1.3, height 8.38
CON_SAMTEC_TSW-103-07-F-S [mm]
  rect 1.85x1.85 / inner round 1.85 / far side rect 1.85x1.85 hole 1 mask+0.05: 1(-2.54,0)
  round 1.85 hole 1 mask+0.05: 2(0,0) 3(2.54,0)
  silkscreen extent -3.85,-1.3 3.85,1.3, body extent -3.91,-1.37 3.91,1.37, height 8.38
CON_SAMTEC_TSW-104-07-G-S [mm]
  rect 1.85x1.85 / inner round 1.85 / far side rect 1.85x1.85 hole 1 mask+0.05: 1(-3.81,0)
  round 1.85 hole 1 mask+0.05: 2(-1.27,0) 3(1.27,0) 4(3.81,0)
  silkscreen extent -5.12,-1.3 5.12,1.3, body extent -5.21,-1.37 5.18,1.37, height 8.38
CON_SAMTEC_TSW-104-07-X-D [mm]
  rect 1.85x1.85 / inner round 1.85 / far side rect 1.85x1.85 hole 1 mask+0.05: 1(-3.81,-1.27)
  round 1.85 hole 1 mask+0.05: 2(-3.81,1.27) 3(-1.27,-1.27) 4(-1.27,1.27) 5(1.27,-1.27) 6(1.27,1.27) 7(3.81,-1.27) 8(3.81,1.27)
  silkscreen extent -5.08,-2.54 5.08,2.54, body extent -5.08,-2.54 5.08,2.54, height 8.38
CON_SAMTEC_TSW-106-07-X-S [mm]
  rect 1.85x1.85 / inner round 1.85 / far side rect 1.85x1.85 hole 1 mask+0.05: 1(-6.35,0)
  round 1.85 hole 1 mask+0.05: 2(-3.81,0) 3(-1.27,0) 4(1.27,0) 5(3.81,0) 6(6.35,0)
  silkscreen extent -7.73,-1.37 7.72,1.37, body extent -7.75,-1.37 7.72,1.37, height 8.38
CON_SAMTEC_TSW-108-07-X-S [mm]
  rect 1.85x1.85 / inner round 1.85 / far side rect 1.85x1.85 hole 1 mask+0.05: 1(-8.89,0)
  round 1.85 hole 1 mask+0.05: 2(-6.35,0) 3(-3.81,0) 4(-1.27,0) 5(1.27,0) 6(3.81,0) 7(6.35,0) 8(8.89,0)
  silkscreen extent -10.27,-1.37 10.26,1.37, body extent -10.29,-1.37 10.26,1.37, height 8.38
CON_SAMTEC_TSW-119-09-X-D [mm]
  rect 1.85x1.85 / inner round 1.85 / far side rect 1.85x1.85 hole 1 mask+0.05: 1(-22.86,-1.27)
  round 1.85 hole 1 mask+0.05: 2(-22.86,1.27) 3(-20.32,-1.27) 4(-20.32,1.27) 5(-17.78,-1.27) 6(-17.78,1.27) 7(-15.24,-1.27) 8(-15.24,1.27) 9(-12.7,-1.27) 10(-12.7,1.27) 11(-10.16,-1.27) 12(-10.16,1.27) 13(-7.62,-1.27) 14(-7.62,1.27) 15(-5.08,-1.27) 16(-5.08,1.27) 17(-2.54,-1.27) 18(-2.54,1.27) 19(0,-1.27) 20(0,1.27) 21(2.54,-1.27) 22(2.54,1.27) 23(5.08,-1.27) 24(5.08,1.27) 25(7.62,-1.27) 26(7.62,1.27) 27(10.16,-1.27) 28(10.16,1.27) 29(12.7,-1.27) 30(12.7,1.27) 31(15.24,-1.27) 32(15.24,1.27) 33(17.78,-1.27) 34(17.78,1.27) 35(20.32,-1.27) 36(20.32,1.27) 37(22.86,-1.27) 38(22.86,1.27)
  silkscreen extent -24.13,-2.54 24.13,2.54, body extent -24.13,-2.55 24.13,2.54, height 8.38
CON_USBMICROB_MOLEX_105017-0001_H2P90 [mm]
  rect 0.4x1.35 smd mask+0.05: 1(-1.3,4.15) 2(-0.65,4.15) 3(0,4.15) 4(0.65,4.15) 5(1.3,4.15)
  round 1.5 hole 0.9 mask+0.05: 6(-2.5,4.15) 7(2.5,4.15)
  oval 1.2x1.9 hole 0.6 slot 1.3 at 90 deg mask+0.05: 8(3.5,1.45) 9(-3.5,1.45)
  rect 1.5x1.9 smd mask+0.05: 10(-1,1.45) 11(1,1.45)
  Top Layer region: -3.5,2.4 -2.3,2.4 -2.3,0.5 -3.5,0.5 -3.5,2.4
  Top Layer region: 2.3,2.4 3.5,2.4 3.5,0.5 2.3,0.5 2.3,2.4
  silkscreen extent -4,-0.7 4,4.6, body extent -4.1,-1.15 4.1,4.66, height 2.9
CRY_NX3215SA_2P [mm]
  rect 1x1.8 smd mask+0.05: 1(-1.25,0) 2(1.25,0)
  silkscreen extent -0.63,-0.8 0.63,0.8, body extent -1.65,-0.8 1.65,0.8, height 0.9
CRY_NX3225GD_2P [mm]
  rect 1.5x2.7 smd mask+0.05: 1(-0.95,0) 2(0.95,0)
  silkscreen extent -0.1,-1.3 0.1,1.3, body extent -1.65,-1.3 1.65,1.3, height 1
DIO_SOD323 [mm]
  rect 1.06x0.54 smd mask+0.05: 1(-1.07,0) 2(1.07,0)
  silkscreen extent -0.9,-0.72 0.9,0.72, body extent -1.3,-0.78 1.3,0.78, height 1.17
ESD_SOT666 [mm]
  rect 0.3x0.99 smd mask+0.05: 1(-0.5,-0.805) 2(0,-0.805) 3(0.5,-0.805) 4(0.5,0.805) 5(0,0.805) 6(-0.5,0.805)
  silkscreen extent -0.85,-0.65 0.85,0.65, body extent -0.85,-0.8 0.85,0.8, height 0.6
ICC_DFN6-EPAD_3X3_P095 [mm]
  rect 0.45x0.5 smd mask+0.05: 1(-0.95,-1.3) 2(0,-1.3) 3(0.95,-1.3) 4(0.95,1.3) 5(0,1.3) 6(-0.95,1.3)
  rect 2.5x1.7 smd mask+0.05: EP(0,0)
  silkscreen extent -1.55,-1.55 1.55,1.55, body extent -1.55,-1.55 1.55,1.55, height 1
ICC_FLIP-CHIP-BGA8_1P11X1P41_P040 [mm]
  round 0.2 smd paste+0 mask+0.05: A1(-0.312,0.5) A3(0.312,0.5) B2(0,0.25) C1(-0.312,0) C3(0.312,0) D2(0,-0.25) E1(-0.312,-0.5) E3(0.312,-0.5)
  silkscreen extent -0.7,-0.72 0.57,0.85, body extent -0.57,-0.72 0.57,0.72, height 0.61
ICC_LQFP48_7X7_P050 [mm]
  rect 0.3x1.2 smd mask+0.05: 1(-2.75,-4.25) 2(-2.25,-4.25) 3(-1.75,-4.25) 4(-1.25,-4.25) 5(-0.75,-4.25) 6(-0.25,-4.25) 7(0.25,-4.25) 8(0.75,-4.25) 9(1.25,-4.25) 10(1.75,-4.25) 11(2.25,-4.25) 12(2.75,-4.25) 25(2.75,4.25) 26(2.25,4.25) 27(1.75,4.25) 28(1.25,4.25) 29(0.75,4.25) 30(0.25,4.25) 31(-0.25,4.25) 32(-0.75,4.25) 33(-1.25,4.25) 34(-1.75,4.25) 35(-2.25,4.25) 36(-2.75,4.25)
  rect 1.2x0.3 smd mask+0.05: 13(4.25,-2.75) 14(4.25,-2.25) 15(4.25,-1.75) 16(4.25,-1.25) 17(4.25,-0.75) 18(4.25,-0.25) 19(4.25,0.25) 20(4.25,0.75) 21(4.25,1.25) 22(4.25,1.75) 23(4.25,2.25) 24(4.25,2.75) 37(-4.25,2.75) 38(-4.25,2.25) 39(-4.25,1.75) 40(-4.25,1.25) 41(-4.25,0.75) 42(-4.25,0.25) 43(-4.25,-0.25) 44(-4.25,-0.75) 45(-4.25,-1.25) 46(-4.25,-1.75) 47(-4.25,-2.25) 48(-4.25,-2.75)
  silkscreen extent -3.52,-3.52 3.52,3.52, body extent -4.5,-4.5 4.5,4.5, height 1.6
ICC_LQFP64_10X10_P050_SOCKET_YAMAICHI_IC149-064-069-B5_NM [mm] "WITH HOLES AND PADS SOCKET BUT SOCKET NO MOUNTED"
  rect 1x2.5 smd rot 45 mask+0.05: 0(-6,-6) 0(6,6)
  rect 1x2.5 smd rot 135 mask+0.05: 0(-6,6) 0(6,-6)
  round 0.5 hole 1 unplated mask+0.05: 0(0,-3.1) 0(0,3.1)
  rect 0.3x1.7 smd mask+0.05: 1(-3.75,-5.9) 2(-3.25,-5.9) 3(-2.75,-5.9) 4(-2.25,-5.9) 5(-1.75,-5.9) 6(-1.25,-5.9) 7(-0.75,-5.9) 8(-0.25,-5.9) 9(0.25,-5.9) 10(0.75,-5.9) 11(1.25,-5.9) 12(1.75,-5.9) 13(2.25,-5.9) 14(2.75,-5.9) 15(3.25,-5.9) 16(3.75,-5.9) 33(3.75,5.9) 34(3.25,5.9) 35(2.75,5.9) 36(2.25,5.9) 37(1.75,5.9) 38(1.25,5.9) 39(0.75,5.9) 40(0.25,5.9) 41(-0.25,5.9) 42(-0.75,5.9) 43(-1.25,5.9) 44(-1.75,5.9) 45(-2.25,5.9) 46(-2.75,5.9) 47(-3.25,5.9) 48(-3.75,5.9)
  rect 1.7x0.3 smd mask+0.05: 17(5.9,-3.75) 18(5.9,-3.25) 19(5.9,-2.75) 20(5.9,-2.25) 21(5.9,-1.75) 22(5.9,-1.25) 23(5.9,-0.75) 24(5.9,-0.25) 25(5.9,0.25) 26(5.9,0.75) 27(5.9,1.25) 28(5.9,1.75) 29(5.9,2.25) 30(5.9,2.75) 31(5.9,3.25) 32(5.9,3.75) 49(-5.9,3.75) 50(-5.9,3.25) 51(-5.9,2.75) 52(-5.9,2.25) 53(-5.9,1.75) 54(-5.9,1.25) 55(-5.9,0.75) 56(-5.9,0.25) 57(-5.9,-0.25) 58(-5.9,-0.75) 59(-5.9,-1.25) 60(-5.9,-1.75) 61(-5.9,-2.25) 62(-5.9,-2.75) 63(-5.9,-3.25) 64(-5.9,-3.75)
  silkscreen extent -5.05,-5.05 5.05,5.05, body extent -6,-6 6,6, height 1.56
ICC_TQFN12_2X1P7_P040 [mm]
  rect 0.2x0.75 smd paste+0 mask+0.05: 1(-0.8,-0.675) 2(-0.4,-0.675) 3(0,-0.675) 4(0.4,-0.675) 5(0.8,-0.675) 7(0.8,0.675) 8(0.4,0.675) 9(0,0.675) 10(-0.4,0.675) 11(-0.8,0.675)
  rect 0.85x0.2 smd paste+0 mask+0.05: 6(0.775,0) 12(-0.775,0)
  silkscreen extent -1.02,-0.85 1.02,0.85, body extent -1,-0.85 1,0.85, height 0.56
ICC_TSSOP16_5P1X4P5_P065 [mm]
  rect 1.65x0.4 smd mask+0.05: 1(-2.8,2.275) 2(-2.8,1.625) 3(-2.8,0.975) 4(-2.8,0.325) 5(-2.8,-0.325) 6(-2.8,-0.975) 7(-2.8,-1.625) 8(-2.8,-2.275) 9(2.8,-2.275) 10(2.8,-1.625) 11(2.8,-0.975) 12(2.8,-0.325) 13(2.8,0.325) 14(2.8,0.975) 15(2.8,1.625) 16(2.8,2.275)
  silkscreen extent -2,-2.55 2,2.55, body extent -3.2,-2.55 3.2,2.55, height 1.2
ICC_VSSOP8_DCU_R-PDSO-G8_2X2P30_P050 [mm]
  rect 0.3x0.8 smd mask+0.05: 1(-0.75,-1.55) 2(-0.25,-1.55) 3(0.25,-1.55) 4(0.75,-1.55) 5(0.75,1.55) 6(0.25,1.55) 7(-0.25,1.55) 8(-0.75,1.55)
  silkscreen extent -1.05,-1.2 1.05,1.2, body extent -1.05,-1.62 1.05,1.62, height 0.9
ICC_WLCSP9_1P65X1P87_P050 [mm]
  round 0.3 smd mask+0.05: A1(-0.5,0.5) A2(0,0.5) A3(0.5,0.5) B1(-0.5,0) B2(0,0) B3(0.5,0) C1(-0.5,-0.5) C2(0,-0.5) C3(0.5,-0.5)
  silkscreen extent -0.97,-0.97 0.85,1.1, body extent -0.85,-0.97 0.85,0.97, height 0.67
IND_TDK_VLS252010HBX-1 [mm]
  rect 0.6x2 smd mask+0.05: 1(-0.95,0) 2(0.95,0)
  silkscreen extent -1.38,-1.12 1.38,1.12, body extent -1.35,-1.1 1.35,1.1, height 1.01
L0603 [mm]
  rect 0.8x0.95 smd mask+0.05: 1(-0.8,0) 2(0.8,0)
  silkscreen extent -1.33,-0.6 1.33,0.6, body extent -0.87,-0.47 0.87,0.47, height 0.95
LED_0603_GREEN [mm]
  rect 0.8x0.8 smd mask+0.05: 1(-0.75,0) 2(0.75,0)
  silkscreen extent -0.25,-0.4 1.25,0.4, body extent -0.8,-0.4 0.8,0.4, height 0.6
LED_0603_RED [mm]
  rect 0.8x0.8 smd mask+0.05: 1(-0.75,0) 2(0.75,0)
  silkscreen extent -0.25,-0.4 1.25,0.4, body extent -0.8,-0.4 0.8,0.4, height 0.6
LED_BI-GR_HSMF-A201-A00J1 [mm]
  rect 1.1x1.5 smd mask+0.05: 1(-0.75,-1.5) 2(-0.75,1.5) 3(0.75,1.5) 4(0.75,-1.5)
  silkscreen extent -1.65,-1.85 1.65,1.85, body extent -1.5,-1.85 1.5,1.85, height 2.1
MIRE_PLACE_SMD_0P8MM [mm]
  round 0.8 smd mask+0.2: 1(0,0)
  Top Layer keep-out circle w0.01: c0,0 r0.804
MOS_SOT23-5L [mm]
  rect 0.6x1.3 smd mask+0.05: 1(-0.95,-1.1) 2(0,-1.1) 3(0.95,-1.1) 4(0.95,1.1) 5(-0.95,1.1)
  silkscreen extent -1.6,-0.95 1.6,0.97, body extent -1.52,-1.25 1.52,1.25, height 1.45
NPN_SOT23 [mm]
  rect 1x1.4 smd mask+0.05: 1(-0.95,-1.1) 2(0.95,-1.1) 3(0,1.1)
  silkscreen extent -1.63,-0.82 1.63,0.82, body extent -1.56,-1.25 1.56,1.25, height 1.1
"NUCLEO_black 0.5cm" [mm]
  silkscreen extent -2.67,-3.86 2.51,1.98
R0603 [mm]
  rect 0.64x1 smd mask+0.05: 1(-0.7,0) 2(0.7,0)
  silkscreen extent -1.05,-0.58 1.05,0.58, body extent -0.9,-0.5 0.9,0.5, height 0.56
REG_SOT23-5L [mm]
  rect 0.6x1.3 smd mask+0.05: 1(-0.95,-1.1) 2(0,-1.1) 3(0.95,-1.1) 4(0.95,1.1) 5(-0.95,1.1)
  silkscreen extent -1.6,-0.95 1.6,0.97, body extent -1.52,-1.25 1.52,1.25, height 1.1
REG_SOT223-TAB [mm]
  rect 1.5x1.65 smd mask+0.05: 1(-2.3,-3.175) 2(0,-3.175) 3(2.3,-3.175)
  rect 3.5x1.65 smd mask+0.05: 4(0,3.175)
  silkscreen extent -3.35,-2.15 3.35,2.12, body extent -3.35,-3.48 3.35,3.48, height 1.8
SOLDER-BRIDGE_R0603-0R [mil]
  round 10 smd paste-393.7: 1(-19.69,0) 2(23.62,0)
  Top Layer region: -47.24,-19.68 -47.24,19.69 -15.75,19.69 3.94,0 -15.75,-19.68 -47.24,-19.68
  Top Layer region: -5.91,19.69 13.78,0 -5.91,-19.68 47.24,-19.68 47.24,19.69 -5.91,19.69
  silkscreen extent -50,-23 50,23, body extent -36,-20 36,20, height 22
SWI_WEALTHMETAL_TD-0341_4P_BLACK [mm]
  rect 1.52x2.16 smd mask+0.05: 1(-2.25,-4.75) 2(-2.25,4.75) 3(2.25,-4.75) 4(2.25,4.75)
  silkscreen extent -3,-3.5 3,3.5, body extent -3,-5.15 3,5.15, height 7.55
SWI_WEALTHMETAL_TD-0341_4P_BLUE [mm]
  rect 1.52x2.16 smd mask+0.05: 1(-2.25,-4.75) 2(-2.25,4.75) 3(2.25,-4.75) 4(2.25,4.75)
  silkscreen extent -3,-3.5 3,3.5, body extent -3,-5.15 3,5.15, height 7.55

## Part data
B1: library part MCD-00002, "Non-Open Push-Button 0.1A 24V"
B2: library part MCD-00001, "Non-Open Push-Button 0.1A 24V BLACK"
C1 C2 C3 C11 C12 C14 C15 C16 C17 C18 C19 C24 C25 C31 C32 C35 C38 C41 C50: library part MCD-00237, "Capacitor, MLCC, 100nF, 6V3, X5R, +/-10%, 0603, T=0.8mm"
C4 C13 C26 C27 C30 C39 C40: library part MCD-00238, "Capacitor, MLCC, 1uF, 6V3, X5R, +/-10%, 0603, T=0,8mm"
C5: library part MCD-00010, "Capacitor, MLCC, 1uF, 16V, X5R, +/-10%, 0603, T=0,8mm"
C6: library part MCD-00211, "Capacitor, MLCC, 100nF, 16V, X7R, +/-10%, 0603, T=0,8mm"
C7 C9: library part MCD-00015, "Capacitor, MLCC, 10pF, 50V, NPO, +/-5%, 0402, T=0,5mm"
C8: library part MCD-00017, "Capacitor, MLCC, 10nF, 50V, X7R, +/-10%, 0603, T=0.8mm"
C10: library part MCD-00638, "Capacitor, MLCC, 20pF, 50V, NPO, +/-5%, 0603, T=0,8mm"
C20 C22: library part MCD-00637, "Capacitor, MLCC, 10pF, 50V, NPO, +/-5%, 0603, T=0,8mm"
C21 C43: library part MCD-00006, "Capacitor, MLCC, 100nF, 16V, X7R, +/-10%, 0402, T=0.5mm"
C23: library part MCD-00555, "Capacitor, MLCC, 22nF, 25V, X7R, +/-10%,0603, T=0,8mm"
C28 C29: library part MCD-00014, "Capacitor, MLCC, 10uF, 25V, X5R, +/-10%, 0805, T=0,85mm"
C33 C34: library part MCD-00273, "Capacitor, MLCC, 1nF, 16V, X7R, +/-10%, 0603, T=0,8mm"
C36: library part MCD-00009, "Capacitor, MLCC, 4.7uF, 16V, X5R, +/-10%, 0603, T=0.8mm"
C37 C42 C44 C49 C51: library part MCD-00243, "Capacitor, MLCC, 10uF, 6V3, X5R, +/-10%, 0603, T=0,8mm"
C45 C46: library part MCD-00674, "Capacitor, MLCC, 6.8pF, 50V, NPO, +/-0.25pF, 0402, T=0.5mm"
C47 C48: library part MCD-00004, "Capacitor, MLCC, 8.2pF, 50V, NPO, +/-4%, 0402, T=0,5mm"
CN1: library part MCD-00028, "USB-MICRO-B, 0.65mm, RA, SMT, Bottom Mount,"
CN2: library part MCD-00029, "Header, 4x1, 2,54mm, VR, TH, Height 5.84mm/2.54mm"
CN3: library part MCD-00212, "Header, 6x1, 2,54mm, VR, TH, Height 5.84mm/2.54mm"
CN4: library part MCD-00032, "Header, 2x1, 2,54mm, VR, TH, Height 5.84mm/2.54mm"
CN5 CN6: library part MCD-00213, "Header, 19x2, 2,54mm, VR, TH, Height 5.84mm/10.16mm"
CN7: library part MCD-00262, "Socket, 10x1, 2.54mm, VR, TH, Height 8.51mm/10mm"
CN8 CN9: library part MCD-00261, "Socket, 8x1, 2.54mm, VR, TH, Height 8.51mm/10mm"
CN10: library part MCD-00260, "Socket, 6x1, 2.54mm, VR, TH, Height 8.51mm/10mm"
CN11: library part MCD-00239, "Header, 8x1, 2,54mm, VR, TH, Height 5.84mm/2.54mm"
D1 D2 D3 D4 D5: library part MCD-00034, "BAT60JFILM"
JP1 JP4 JP6 JP8: library part MCD-00045, "Header, 2x1, 2,54mm, VR, TH, Height 5.84mm/2.54mm"
JP2 JP3: library part MCD-00214, "Header, 2x1, 2,54mm, VR, TH, Height 5.84mm/10.16mm"
JP5: library part MCD-00633, "Header, 4x2, 2,54mm, VR, TH, Height 5.84mm/2.54mm"
JP7: library part MCD-00111, "Header, 3x1, 2,54mm, VR, TH, Height 5.84mm/2.54mm"
L1 L3: library part MCD-00240, "FIXED IND 2.2UH 2.6A 100 mOHM 20% SMD"
L2: library part MCD-00047, "SMD Chip ferrite bead, 600R@100MHz +/-25%, 350mA, 500mohm DC, 0603, T=0.8mm"
LD1: library part MCD-02360, "Led, Bi-color Red/Green, 2V4, 30mA, 4-PLCC"
LD2: library part MCD-02899, "LED, Red, VF : Min=1.75V , Max=2.35V, 25mA, 0603"
LD3 LD4: library part MCD-02900, "LED, Green, 2V, 25mA, 0603, SMD"
Q1 Q2: library part MCD-00073, "NPN Bipolar Transistor"
R1 R26 R41 R42 R44: library part MCD-00056, "Resistor,0R,0603,5%,1/10W"
R2 R5 R28 R33: library part MCD-00223, "Resistor,100K,0603,1%,1/10W"
R3 R4 R8 R13 R25 R32: library part MCD-00220, "Resistor,10K,0603,1%,1/10W"
R6 R22 R24: library part MCD-00219, "Resistor,4K7,0603,1%,1/10W"
R7: library part MCD-00218, "Resistor,2K7,0603,1%,1/10W"
R9 R10 R38: library part MCD-00197, "Resistor,330R,0603,1%,1/10W"
R11 R14 R17 R20: library part MCD-00066, "Resistor,22R,0603,1%,1/10W"
R12: library part MCD-00217, "Resistor,1K5,0603,1%,1/10W"
R15: library part MCD-00221, "Resistor,36K,0603,1%,1/10W"
R16 R18 R19 R23: library part MCD-00224, "Resistor,100R,0603,1%,1/10W"
R21 R30 R31 R35: library part MCD-00070, "Resistor,1K,0603,1%,1/10W"
R29 R34: library part MCD-00225, "Resistor,510R,0603,1%,1/10W"
R36: library part MCD-00222, "Resistor,47K,0603,1%,1/10W"
R37: library part MCD-00241, "Resistor,3M3,0603,1%,1/10W"
R39: library part MCD-00546, "Resistor,25K5,0603,1%,1/10W"
R40: library part MCD-00257, "Resistor,1M,0603,1%,1/10W"
R43: library part MCD-00242, "Resistor,19K6,0603,1%,1/10W"
SB1 SB2 SB3 SB4 SB5 SB6 SB7 SB8 SB9 SB10 SB11 SB12 SB13 SB14 SB15 SB16 SB17 SB18 SB19 SB20 SB21 SB22 SB23 SB24 SB25 SB26 SB27 SB28 SB29 SB30 SB31 SB32 SB33 SB34 SB35 SB36 SB37 SB38 SB39 SB40 SB41 SB42 SB43 SB44 SB45 SB46 SB47 SB48 SB49 SB50 SB51 SB52 SB53 SB54 SB55 SB56 SB57 SB58 SB59 SB60 SB61 SB62 SB63 SB64 SB65 SB66 SB67 SB68 SB69 SB70 SB71 SB72 SB73 SB74 SB75 SB76 SB77 SB78 SB79 SB80 SB81 SB82 SB83 SB84 SB85 SB86 SB87 SB88 SB89 SB90 SB91 SB92 SB93 SB94 SB95 SB96 SB97: library part MCD-00071, "Solder Bridge ON"
U1: library part MCD-00169, "USB OTG FS ESD protection"
U2: library part MCD-00085, "Medium-density performance line ARM-based 32-bit MCU with 128KB Flash"
U3: library part MCD-00086, "Ultra low drop-low noise BiCMOS voltage, regulators low ESR capacitors compatible"
U4: library part MCD-00083, "Enhanced single channel power switches with active low enable pin"
U5 U6: library part MCD-00264, "Dual bit dual supply bus transceiver"
U7: library part MCD-00215, "Low quiescent current and low noise voltage regulators"
U8: library part MCD-00088, "IC REG LDO 5V 0.8A SOT223"
U9: library part MCD-00548, "STM32L433RCT6P: External SMPS configuration. LQFP64 package"
U10: library part MCD-00090, "SPDT analog switch 4-Channel 2:1 bidirectional"
U11: library part MCD-00230, "UL Step down regulator: Opt1"
U12: library part MCD-00229, "400mA Nano-Quiescent Step down converter with Aux switch"
U13: library part MCD-00226, "UL Step down regulator: Opt0"
U14: library part MCD-00228, "400mA Nano-Quiescent Step down converter"
X1 X2: library part MCD-00092, "Crystal 8MHz, 8pF, +-20ppm, 500ohms max,  SMD"
X3: library part MCD-00091, "Crystal 32.768kHz, 6pF, +-20ppm, 50Kohms max, SMD"

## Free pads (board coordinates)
  round 3.2 hole 3.2 unplated: 0(0,49.53) 0(33.02,-2.54) 0(48.26,48.26)

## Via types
v1: diameter 0.4, hole 0.2, Top Layer to Bottom Layer, tented both sides, 802 vias
v2: diameter 0.6, hole 0.3, Top Layer to Bottom Layer, tented both sides, 198 vias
